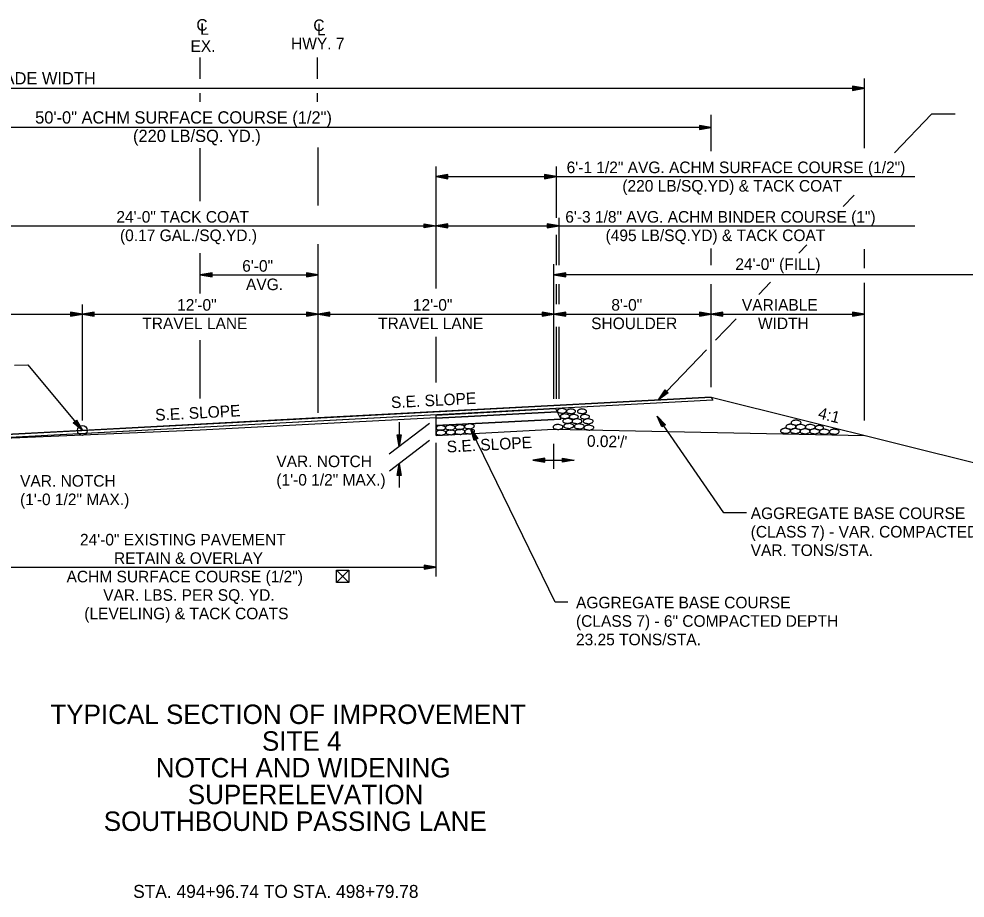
# Model space of a CAD drawing. Extents: x 1398183 to 1398373, y 1967240 to 1968889.
# Drawn here: x 1398245.63 to 1398293.78, y 1967444.87 to 1967489.63 of the extents above; entities that cross this region are included whole.
import ezdxf

# ---------------------------------------------------------------- set-up
doc = ezdxf.new("R2010")
doc.units = 0
for name, color, linetype in [('1', 7, 'Continuous'), ('10', 7, 'Continuous'), ('19', 7, 'Continuous'), ('42', 7, 'Continuous'), ('7', 7, 'Continuous'), ('Level 1', 7, 'Continuous'), ('Level 9', 7, 'Continuous')]:
    doc.layers.add(name, color=color, linetype=linetype)

# ---------------------------------------------------------------- blocks, each defined once
blk = doc.blocks.new('ROCKS')
at = {"layer": '1'}
blk.add_spline([(0.013, 0.06), (0.053, 0.053), (0.107, 0.033), (0.133, 0.013), (0.133, -0.007), (0.12, -0.033), (0.107, -0.04), (0.073, -0.053), (0.033, -0.067), (0.013, -0.067), (-0.02, -0.06), (-0.06, -0.053), (-0.087, -0.047), (-0.113, -0.02), (-0.113, -0.007), (-0.107, 0.02), (-0.087, 0.033), (-0.067, 0.047), (-0.033, 0.053), (-0.02, 0.06), (0.013, 0.06)], degree=3, dxfattribs=at)

msp = doc.modelspace()

# ---------------------------------------------------------------- linework, layer by layer
at = {"layer": '10'}
for p, q in [((1398262.427, 1967461.569), (1398261.786, 1967460.928)), ((1398261.786, 1967461.569), (1398262.427, 1967460.928)), ((1398262.046, 1967460.928), (1398262.034, 1967460.928))]:
    msp.add_line(p, q, dxfattribs=at)
msp.add_lwpolyline([(1398262.034, 1967460.928), (1398261.786, 1967460.928), (1398261.786, 1967461.569), (1398262.427, 1967461.569), (1398262.427, 1967460.928), (1398262.046, 1967460.928)], dxfattribs=at)
at = {"layer": '19'}
for p, q in [((1398288.661, 1967483.056), (1398288.661, 1967486.608)), ((1398224.719, 1967486.102), (1398288.661, 1967486.102)), ((1398288.061, 1967486.207), (1398288.061, 1967485.997)), ((1398288.661, 1967486.102), (1398288.061, 1967486.207)), ((1398288.501, 1967486.117), (1398288.061, 1967486.152)), ((1398288.061, 1967485.997), (1398288.661, 1967486.102)), ((1398288.061, 1967486.047), (1398288.501, 1967486.087)), ((1398280.864, 1967482.891), (1398280.864, 1967484.749)), ((1398280.864, 1967484.102), (1398230.863, 1967484.102)), ((1398280.264, 1967484.207), (1398280.264, 1967483.997)), ((1398280.864, 1967484.102), (1398280.264, 1967484.207)), ((1398280.704, 1967484.117), (1398280.264, 1967484.152)), ((1398280.264, 1967483.997), (1398280.864, 1967484.102)), ((1398280.264, 1967484.047), (1398280.704, 1967484.087)), ((1398266.861, 1967475.898), (1398266.861, 1967482.12)), ((1398267.461, 1967481.707), (1398266.861, 1967481.602)), ((1398267.461, 1967481.497), (1398267.461, 1967481.707)), ((1398272.386, 1967481.707), (1398272.386, 1967481.497)), ((1398272.986, 1967481.602), (1398272.386, 1967481.707)), ((1398272.986, 1967479.511), (1398272.986, 1967482.12)), ((1398266.861, 1967481.602), (1398291.231, 1967481.602)), ((1398266.861, 1967481.602), (1398267.461, 1967481.497)), ((1398267.461, 1967481.652), (1398267.021, 1967481.617)), ((1398267.021, 1967481.587), (1398267.461, 1967481.547)), ((1398272.826, 1967481.617), (1398272.386, 1967481.652)), ((1398272.386, 1967481.497), (1398272.986, 1967481.602)), ((1398272.386, 1967481.547), (1398272.826, 1967481.587)), ((1398273.121, 1967477.089), (1398273.121, 1967479.511)), ((1398242.861, 1967479.102), (1398291.231, 1967479.102)), ((1398266.261, 1967478.997), (1398266.261, 1967479.207)), ((1398266.261, 1967479.207), (1398266.861, 1967479.102)), ((1398266.261, 1967479.152), (1398266.701, 1967479.117)), ((1398266.861, 1967479.102), (1398266.261, 1967478.997)), ((1398266.701, 1967479.087), (1398266.261, 1967479.047)), ((1398267.461, 1967479.207), (1398266.861, 1967479.102)), ((1398266.861, 1967479.102), (1398267.461, 1967478.997)), ((1398267.461, 1967479.152), (1398267.021, 1967479.117)), ((1398267.021, 1967479.087), (1398267.461, 1967479.047)), ((1398267.461, 1967478.997), (1398267.461, 1967479.207)), ((1398272.521, 1967479.207), (1398272.521, 1967478.997)), ((1398273.121, 1967479.102), (1398272.521, 1967479.207)), ((1398272.961, 1967479.117), (1398272.521, 1967479.152)), ((1398272.521, 1967478.997), (1398273.121, 1967479.102)), ((1398272.521, 1967479.047), (1398272.961, 1967479.087)), ((1398272.986, 1967477.089), (1398272.986, 1967478.643)), ((1398280.863, 1967477.089), (1398280.863, 1967477.935)), ((1398288.661, 1967476.944), (1398288.661, 1967477.902)), ((1398272.861, 1967470.296), (1398272.861, 1967477.149)), ((1398255.461, 1967476.707), (1398254.861, 1967476.602)), ((1398254.861, 1967476.602), (1398260.861, 1967476.602)), ((1398254.861, 1967476.602), (1398255.461, 1967476.497)), ((1398255.461, 1967476.652), (1398255.021, 1967476.617)), ((1398255.021, 1967476.587), (1398255.461, 1967476.547)), ((1398255.461, 1967476.497), (1398255.461, 1967476.707)), ((1398260.261, 1967476.707), (1398260.261, 1967476.497)), ((1398260.861, 1967476.602), (1398260.261, 1967476.707)), ((1398260.701, 1967476.617), (1398260.261, 1967476.652)), ((1398260.261, 1967476.497), (1398260.861, 1967476.602)), ((1398260.261, 1967476.547), (1398260.701, 1967476.587)), ((1398273.461, 1967476.707), (1398272.861, 1967476.602)), ((1398296.861, 1967476.602), (1398272.861, 1967476.602)), ((1398272.861, 1967476.602), (1398273.461, 1967476.497)), ((1398273.461, 1967476.652), (1398273.021, 1967476.617)), ((1398273.021, 1967476.587), (1398273.461, 1967476.547)), ((1398273.461, 1967476.497), (1398273.461, 1967476.707)), ((1398272.986, 1967475.106), (1398272.986, 1967476.122)), ((1398273.121, 1967475.106), (1398273.121, 1967476.122)), ((1398280.861, 1967470.874), (1398280.861, 1967476.122)), ((1398288.661, 1967469.187), (1398288.661, 1967476.188)), ((1398248.861, 1967469.178), (1398248.861, 1967475.09)), ((1398236.861, 1967474.602), (1398248.861, 1967474.602)), ((1398248.261, 1967474.707), (1398248.261, 1967474.497)), ((1398248.861, 1967474.602), (1398248.261, 1967474.707)), ((1398248.701, 1967474.617), (1398248.261, 1967474.652)), ((1398248.261, 1967474.497), (1398248.861, 1967474.602)), ((1398248.261, 1967474.547), (1398248.701, 1967474.587)), ((1398249.461, 1967474.707), (1398248.861, 1967474.602)), ((1398248.861, 1967474.602), (1398249.461, 1967474.497)), ((1398248.861, 1967474.602), (1398260.861, 1967474.602)), ((1398249.461, 1967474.652), (1398249.021, 1967474.617)), ((1398249.021, 1967474.587), (1398249.461, 1967474.547)), ((1398249.461, 1967474.497), (1398249.461, 1967474.707)), ((1398260.261, 1967474.707), (1398260.261, 1967474.497)), ((1398260.861, 1967474.602), (1398260.261, 1967474.707)), ((1398260.701, 1967474.617), (1398260.261, 1967474.652)), ((1398260.261, 1967474.497), (1398260.861, 1967474.602)), ((1398260.261, 1967474.547), (1398260.701, 1967474.587)), ((1398261.461, 1967474.707), (1398260.861, 1967474.602)), ((1398260.861, 1967474.602), (1398261.461, 1967474.497)), ((1398260.861, 1967474.602), (1398272.861, 1967474.602)), ((1398261.461, 1967474.652), (1398261.021, 1967474.617)), ((1398261.021, 1967474.587), (1398261.461, 1967474.547)), ((1398261.461, 1967474.497), (1398261.461, 1967474.707)), ((1398272.261, 1967474.707), (1398272.261, 1967474.497)), ((1398272.861, 1967474.602), (1398272.261, 1967474.707)), ((1398272.701, 1967474.617), (1398272.261, 1967474.652)), ((1398272.261, 1967474.497), (1398272.861, 1967474.602)), ((1398272.261, 1967474.547), (1398272.701, 1967474.587)), ((1398273.461, 1967474.707), (1398272.861, 1967474.602)), ((1398272.861, 1967474.602), (1398273.461, 1967474.497)), ((1398272.861, 1967474.602), (1398280.861, 1967474.602)), ((1398273.461, 1967474.652), (1398273.021, 1967474.617)), ((1398273.021, 1967474.587), (1398273.461, 1967474.547)), ((1398273.461, 1967474.497), (1398273.461, 1967474.707)), ((1398280.261, 1967474.707), (1398280.261, 1967474.497)), ((1398280.861, 1967474.602), (1398280.261, 1967474.707)), ((1398280.701, 1967474.617), (1398280.261, 1967474.652)), ((1398280.261, 1967474.497), (1398280.861, 1967474.602)), ((1398280.261, 1967474.547), (1398280.701, 1967474.587)), ((1398281.461, 1967474.707), (1398280.861, 1967474.602)), ((1398280.861, 1967474.602), (1398288.661, 1967474.602)), ((1398280.861, 1967474.602), (1398281.461, 1967474.497)), ((1398281.461, 1967474.652), (1398281.021, 1967474.617)), ((1398281.021, 1967474.587), (1398281.461, 1967474.547)), ((1398281.461, 1967474.497), (1398281.461, 1967474.707)), ((1398288.061, 1967474.707), (1398288.061, 1967474.497)), ((1398288.661, 1967474.602), (1398288.061, 1967474.707)), ((1398288.501, 1967474.617), (1398288.061, 1967474.652)), ((1398288.061, 1967474.497), (1398288.661, 1967474.602)), ((1398288.061, 1967474.547), (1398288.501, 1967474.587)), ((1398272.986, 1967470.296), (1398272.986, 1967473.947)), ((1398273.121, 1967470.296), (1398273.121, 1967473.947)), ((1398266.861, 1967471.125), (1398266.861, 1967473.437)), ((1398278.184, 1967470.232), (1398278.516, 1967470.743)), ((1398278.668, 1967470.6), (1398278.184, 1967470.232)), ((1398278.283, 1967470.357), (1398278.553, 1967470.705)), ((1398278.631, 1967470.633), (1398278.304, 1967470.338)), ((1398278.516, 1967470.743), (1398278.668, 1967470.6)), ((1398280.861, 1967470.374), (1398296.861, 1967466.374)), ((1398280.861, 1967470.374), (1398280.942, 1967470.212)), ((1398272.942, 1967469.788), (1398273.207, 1967469.259)), ((1398248.397, 1967469.072), (1398248.558, 1967469.205)), ((1398248.525, 1967469.173), (1398248.77, 1967468.811)), ((1398248.558, 1967469.205), (1398248.861, 1967468.678)), ((1398266.861, 1967469.298), (1398273.024, 1967469.625)), ((1398266.861, 1967468.422), (1398266.861, 1967469.465)), ((1398266.861, 1967468.923), (1398273.207, 1967469.259)), ((1398278.358, 1967468.854), (1398278.105, 1967469.406)), ((1398278.105, 1967469.406), (1398278.531, 1967468.971)), ((1398281.504, 1967464.488), (1398278.105, 1967469.406)), ((1398278.399, 1967468.882), (1398278.182, 1967469.266)), ((1398278.205, 1967469.282), (1398278.486, 1967468.943)), ((1398248.861, 1967468.678), (1398248.397, 1967469.072)), ((1398248.752, 1967468.793), (1398248.441, 1967469.102)), ((1398266.521, 1967469.038), (1398264.477, 1967467.474)), ((1398264.979, 1967469.106), (1398264.979, 1967467.858)), ((1398266.861, 1967468.422), (1398272.861, 1967468.74)), ((1398272.918, 1967459.94), (1398268.629, 1967468.75)), ((1398268.806, 1967468.169), (1398268.629, 1967468.75)), ((1398268.629, 1967468.75), (1398268.993, 1967468.261)), ((1398272.861, 1967468.74), (1398288.661, 1967468.424)), ((1398278.531, 1967468.971), (1398278.358, 1967468.854)), ((1398264.874, 1967468.458), (1398265.084, 1967468.458)), ((1398264.979, 1967467.858), (1398264.874, 1967468.458)), ((1398264.964, 1967468.018), (1398264.924, 1967468.458)), ((1398265.084, 1967468.458), (1398264.979, 1967467.858)), ((1398265.029, 1967468.458), (1398264.994, 1967468.018)), ((1398268.85, 1967468.191), (1398268.687, 1967468.6)), ((1398268.712, 1967468.613), (1398268.944, 1967468.24)), ((1398268.993, 1967468.261), (1398268.806, 1967468.169)), ((1398266.524, 1967468.165), (1398264.498, 1967466.613)), ((1398266.861, 1967461.246), (1398266.861, 1967468.041)), ((1398264.874, 1967466.382), (1398264.979, 1967466.982)), ((1398264.924, 1967466.382), (1398264.964, 1967466.822)), ((1398264.979, 1967466.982), (1398265.084, 1967466.382)), ((1398264.979, 1967466.982), (1398264.979, 1967465.781)), ((1398264.994, 1967466.822), (1398265.029, 1967466.382)), ((1398265.084, 1967466.382), (1398264.874, 1967466.382)), ((1398282.655, 1967464.488), (1398281.504, 1967464.488)), ((1398242.861, 1967461.716), (1398266.861, 1967461.716)), ((1398266.261, 1967461.821), (1398266.261, 1967461.611)), ((1398266.861, 1967461.716), (1398266.261, 1967461.821)), ((1398266.701, 1967461.731), (1398266.261, 1967461.766)), ((1398266.261, 1967461.611), (1398266.861, 1967461.716)), ((1398266.261, 1967461.661), (1398266.701, 1967461.701)), ((1398273.565, 1967459.94), (1398272.918, 1967459.94))]:
    msp.add_line(p, q, dxfattribs=at)
for points in [[(1398293.282, 1967484.79), (1398292.074, 1967484.79), (1398290.194, 1967482.818)], [(1398288.142, 1967480.664), (1398287.579, 1967480.074)], [(1398285.733, 1967478.131), (1398285.326, 1967477.706)], [(1398283.874, 1967476.225), (1398283.287, 1967475.607)], [(1398282.128, 1967474.362), (1398282.128, 1967474.362), (1398281.081, 1967473.275)], [(1398280.625, 1967472.788), (1398280.625, 1967472.788), (1398278.184, 1967470.232)], [(1398245.412, 1967472.006), (1398246.079, 1967472.018), (1398248.861, 1967468.678)], [(1398280.942, 1967470.212), (1398236.87, 1967467.876), (1398230.775, 1967467.553)], [(1398280.861, 1967470.374), (1398272.861, 1967469.95), (1398260.861, 1967469.314), (1398248.861, 1967468.678), (1398236.861, 1967468.042), (1398230.861, 1967467.724)]]:
    msp.add_lwpolyline(points, dxfattribs=at)
for points in [[(1398230.861, 1967467.724), (1398280.861, 1967470.374), (1398280.942, 1967470.212), (1398230.775, 1967467.553)], [(1398266.861, 1967469.465), (1398272.942, 1967469.788), (1398273.024, 1967469.625), (1398266.861, 1967469.298)], [(1398266.861, 1967469.298), (1398273.024, 1967469.625), (1398273.207, 1967469.259), (1398266.861, 1967468.923)]]:
    msp.add_lwpolyline(points, close=True, dxfattribs=at)
at = {"layer": '42'}
for p, q in [((1398272.841, 1967468.001), (1398272.841, 1967466.718)), ((1398272.393, 1967467.275), (1398271.793, 1967467.17)), ((1398272.393, 1967467.065), (1398272.393, 1967467.275)), ((1398273.288, 1967467.065), (1398273.288, 1967467.275)), ((1398273.288, 1967467.275), (1398273.888, 1967467.17)), ((1398271.793, 1967467.17), (1398272.393, 1967467.065)), ((1398271.793, 1967467.17), (1398273.888, 1967467.17)), ((1398272.393, 1967467.22), (1398271.953, 1967467.185)), ((1398271.953, 1967467.155), (1398272.393, 1967467.115)), ((1398273.288, 1967467.22), (1398273.728, 1967467.185)), ((1398273.888, 1967467.17), (1398273.288, 1967467.065)), ((1398273.728, 1967467.155), (1398273.288, 1967467.115))]:
    msp.add_line(p, q, dxfattribs=at)
msp.add_lwpolyline([(1398242.861, 1967468.193), (1398254.861, 1967468.712), (1398266.861, 1967469.338)], dxfattribs=at)
at = {"layer": '7'}
for p, q in [((1398254.86, 1967486.587), (1398254.86, 1967487.671)), ((1398260.819, 1967486.587), (1398260.819, 1967487.671)), ((1398254.86, 1967485.407), (1398254.86, 1967485.856)), ((1398260.819, 1967485.407), (1398260.819, 1967485.857)), ((1398254.861, 1967480.36), (1398254.86, 1967483.046)), ((1398260.861, 1967480.135), (1398260.86, 1967483.083)), ((1398260.861, 1967469.581), (1398260.861, 1967478.161)), ((1398254.861, 1967475.648), (1398254.861, 1967477.71)), ((1398254.861, 1967470.302), (1398254.861, 1967473.279))]:
    msp.add_line(p, q, dxfattribs=at)
at = {"layer": 'Level 9'}
msp.add_circle((1398248.861, 1967468.678), 0.25, dxfattribs=at)

# ---------------------------------------------------------------- block references
at = {"layer": 'Level 1'}
for p, xscale, yscale, rotation in [((1398273.249, 1967469.682), 1.8771740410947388, 1.8771740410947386, -0.173618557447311), ((1398273.706, 1967469.657), 1.849824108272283, 1.8498241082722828, -0.17361855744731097), ((1398274.271, 1967469.657), 1.849824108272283, 1.8498241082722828, -0.17361855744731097), ((1398273.397, 1967469.404), 1.8771740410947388, 1.8771740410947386, -0.173618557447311), ((1398273.54, 1967469.169), 2.011654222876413, 2.0116542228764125, -0.17361855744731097), ((1398273.854, 1967469.379), 1.849824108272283, 1.8498241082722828, -0.17361855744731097), ((1398274.017, 1967469.155), 2.011654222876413, 2.0116542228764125, -0.17361855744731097), ((1398274.418, 1967469.379), 1.849824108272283, 1.8498241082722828, -0.17361855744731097), ((1398274.582, 1967469.155), 2.011654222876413, 2.0116542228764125, -0.17361855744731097), ((1398285.164, 1967469.082), 2.011654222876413, 2.0116542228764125, -0.17361855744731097), ((1398267.084, 1967468.57), 1.9974694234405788, 1.9974694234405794, 0.7393721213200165), ((1398267.089, 1967468.817), 1.9070518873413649, 1.907051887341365, 0.7393721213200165), ((1398267.565, 1967468.831), 1.9598639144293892, 1.9598639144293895, 0.7393721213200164), ((1398267.581, 1967468.587), 1.8902055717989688, 1.8902055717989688, 0.7393721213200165), ((1398268.054, 1967468.612), 2.0116542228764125, 2.011654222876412, 2.739372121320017), ((1398268.052, 1967468.847), 1.900874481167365, 1.9008744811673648, 2.7393721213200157), ((1398268.539, 1967468.892), 2.0116542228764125, 2.011654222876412, 2.739372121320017), ((1398268.549, 1967468.634), 2.0116542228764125, 2.011654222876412, 2.739372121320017), ((1398273.048, 1967468.863), 2.011654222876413, 2.0116542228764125, -0.17361855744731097), ((1398273.594, 1967468.915), 2.011654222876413, 2.0116542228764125, -0.17361855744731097), ((1398274.127, 1967468.891), 2.011654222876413, 2.0116542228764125, -0.17361855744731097), ((1398274.616, 1967468.831), 2.011654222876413, 2.0116542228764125, -0.17361855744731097), ((1398284.625, 1967468.668), 2.011654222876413, 2.0116542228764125, -0.17361855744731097), ((1398284.625, 1967468.668), 2.011654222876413, 2.0116542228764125, -0.17361855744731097), ((1398284.895, 1967468.875), 2.011654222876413, 2.0116542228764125, -0.17361855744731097), ((1398285.13, 1967468.658), 2.011654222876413, 2.0116542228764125, -0.17361855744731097), ((1398285.13, 1967468.658), 2.011654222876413, 2.0116542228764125, -0.17361855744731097), ((1398285.396, 1967468.863), 2.011654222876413, 2.0116542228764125, -0.17361855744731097), ((1398285.622, 1967468.639), 2.011654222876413, 2.0116542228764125, -0.17361855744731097), ((1398285.622, 1967468.639), 2.011654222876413, 2.0116542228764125, -0.17361855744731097), ((1398285.891, 1967468.863), 2.011654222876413, 2.0116542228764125, -0.17361855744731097), ((1398286.111, 1967468.639), 2.011654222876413, 2.0116542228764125, -0.17361855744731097), ((1398286.111, 1967468.639), 2.011654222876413, 2.0116542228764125, -0.17361855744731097), ((1398286.353, 1967468.824), 1.7335100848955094, 1.7335100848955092, -0.173618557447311), ((1398286.605, 1967468.62), 2.011654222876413, 2.0116542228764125, -0.17361855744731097), ((1398286.605, 1967468.62), 2.011654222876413, 2.0116542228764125, -0.17361855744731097), ((1398287.107, 1967468.62), 2.011654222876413, 2.0116542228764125, -0.17361855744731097), ((1398287.107, 1967468.62), 2.011654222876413, 2.0116542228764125, -0.17361855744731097)]:
    msp.add_blockref('ROCKS', p, dxfattribs=dict(at, xscale=xscale, yscale=yscale, rotation=rotation))

# ---------------------------------------------------------------- texts
at = {"layer": '10'}
for s, height, p in [('24\'-0" (FILL)', 0.59001, (1398282.092, 1967476.853)), ('12\'-0"', 0.59, (1398253.683, 1967474.777)), ('12\'-0"', 0.59, (1398265.683, 1967474.777)), ('8\'-0"', 0.59, (1398275.781, 1967474.777)), ('VARIABLE', 0.59, (1398282.425, 1967474.777)), ('TRAVEL LANE', 0.59001, (1398251.911, 1967473.837)), ('TRAVEL LANE', 0.59001, (1398263.911, 1967473.837)), ('SHOULDER', 0.59, (1398274.754, 1967473.837)), ('WIDTH', 0.59, (1398283.242, 1967473.837)), ('VAR. NOTCH', 0.59, (1398258.732, 1967466.81)), ('VAR. NOTCH', 0.59, (1398245.69, 1967465.815)), ('(1\'-0 1/2" MAX.)', 0.59001, (1398258.732, 1967465.87)), ('(1\'-0 1/2" MAX.)', 0.59001, (1398245.69, 1967464.875))]:
    msp.add_text(s, height=height, dxfattribs=at).set_placement(p)
for s, height, rotation, p in [('4:1', 0.59, 345.9638, (1398286.264, 1967469.3)), ('24\'-0" EXISTING PAVEMENT', 0.59001, 0, (1398248.737, 1967462.823)), ('RETAIN & OVERLAY', 0.59001, 0, (1398250.467, 1967461.883)), ('ACHM SURFACE COURSE (1/2")', 0.59001, 0, (1398248.056, 1967460.943)), ('VAR. LBS. PER SQ. YD.', 0.59001, 0, (1398249.919, 1967460.003)), ('(LEVELING) & TACK COATS', 0.59001, 0, (1398248.958, 1967459.063))]:
    msp.add_text(s, height=height, rotation=rotation, dxfattribs=at).set_placement(p)
at = {"layer": '19'}
for s, height, p in [('C', 0.59, (1398254.663, 1967489.035)), ('L', 0.59, (1398254.857, 1967488.824)), ('C', 0.59, (1398260.614, 1967489.016)), ('L', 0.59, (1398260.802, 1967488.805)), ('HWY. 7', 0.59, (1398259.483, 1967488.086)), ('VAR. SUBGRADE WIDTH', 0.625, (1398239.697, 1967486.299)), ('50\'-0" ACHM SURFACE COURSE (1/2")', 0.625, (1398246.457, 1967484.305)), ('(220 LB/SQ. YD.)', 0.625, (1398251.437, 1967483.367)), ('TYPICAL SECTION OF IMPROVEMENT', 0.98999, (1398247.231, 1967453.731)), ('SITE 4', 0.99, (1398258, 1967452.37)), ('NOTCH AND WIDENING', 0.98999, (1398252.594, 1967451.009)), ('SUPERELEVATION', 0.98999, (1398254.224, 1967449.648)), ('SOUTHBOUND PASSING LANE', 0.98999, (1398249.948, 1967448.286)), ('STA. 494+96.74 TO STA. 498+79.78', 0.65999, (1398251.445, 1967444.876))]:
    msp.add_text(s, height=height, dxfattribs=at).set_placement(p)
for s, height, rotation, p in [('EX.', 0.59, 0, (1398254.363, 1967487.957)), ('6\'-0"', 0.59, 0, (1398256.995, 1967476.762)), ('AVG.', 0.59, 0, (1398257.188, 1967475.822)), ('S.E. SLOPE', 0.59, 3.0338, (1398264.581, 1967469.807)), ('S.E. SLOPE', 0.59, 3.0338, (1398252.581, 1967469.171)), ('S.E. SLOPE', 0.59, 3.0338, (1398267.419, 1967467.554)), ("0.02'/'", 0.59, 358.8542, (1398274.532, 1967467.85)), ('AGGREGATE BASE COURSE', 0.59001, 360, (1398282.874, 1967464.166)), ('(CLASS 7) - VAR. COMPACTED DEPTH', 0.59001, 360, (1398282.874, 1967463.226)), ('VAR. TONS/STA.', 0.59001, 360, (1398282.874, 1967462.286)), ('AGGREGATE BASE COURSE', 0.59001, 360, (1398273.983, 1967459.62)), ('(CLASS 7) - 6" COMPACTED DEPTH', 0.59001, 360, (1398273.983, 1967458.68)), ('23.25 TONS/STA.', 0.59001, 360, (1398273.983, 1967457.74))]:
    msp.add_text(s, height=height, rotation=rotation, dxfattribs=at).set_placement(p)
at = {"layer": '42'}
for s, p in [('6\'-1 1/2" AVG. ACHM SURFACE COURSE (1/2")', (1398273.505, 1967481.78)), ('(220 LB/SQ.YD) & TACK COAT', (1398276.341, 1967480.84)), ('24\'-0" TACK COAT', (1398250.591, 1967479.26)), ('6\'-3 1/8" AVG. ACHM BINDER COURSE (1")', (1398273.437, 1967479.26)), ('(0.17 GAL./SQ.YD.)', (1398250.775, 1967478.32)), ('(495 LB/SQ.YD) & TACK COAT', (1398275.488, 1967478.32))]:
    msp.add_text(s, height=0.59001, rotation=360, dxfattribs=at).set_placement(p)

doc.saveas('drawing.dxf')
